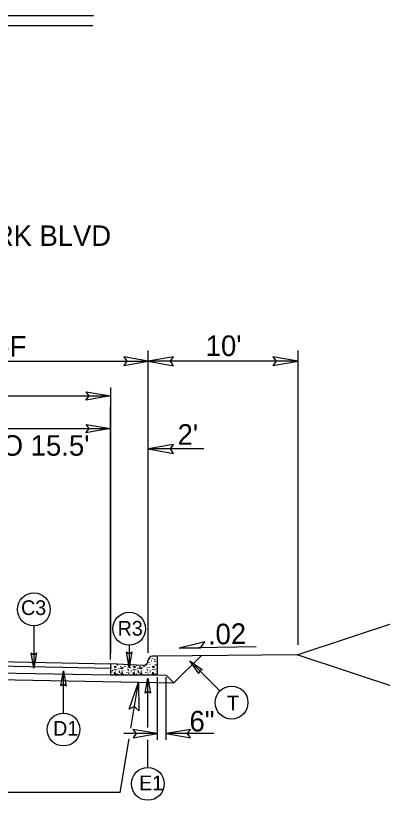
# Model space of a CAD drawing. Extents: x 958711 to 962106, y 831169 to 840840.
# Drawn here: x 959584.1 to 959723.1, y 835320.7 to 835618.4 of the extents above; entities that cross this region are included whole.
import ezdxf

# ---------------------------------------------------------------- set-up
doc = ezdxf.new("R2010")
doc.units = 0
for name, color, linetype in [('Old_Level_1', 7, 'Continuous'), ('Old_Level_11', 7, 'Continuous'), ('Old_Level_3', 7, 'Continuous'), ('Prop Dimension Text', 7, 'Continuous'), ('Typical ID Circle CELL', 7, 'Continuous'), ('Typical Terminator CELL', 7, 'Continuous'), ('Typical Text ID Circle CELL', 7, 'Continuous')]:
    doc.layers.add(name, color=color, linetype=linetype)

msp = doc.modelspace()

# ---------------------------------------------------------------- linework, layer by layer
at = {"layer": 'Old_Level_1'}
for p, q in [((959613.61, 835618.38), (959445.91, 835618.38)), ((959613.32, 835614.57), (959445.63, 835614.57)), ((959634.32, 835376.63), (959634.32, 835491.34)), ((959691.28, 835379.65), (959691.28, 835491.34)), ((959418.82, 835487.29), (959634.32, 835487.29)), ((959691.28, 835487.29), (959634.32, 835487.29)), ((959620.02, 835477.34), (959620.02, 835376.49)), ((959433.06, 835474.09), (959620.02, 835474.09)), ((959620.02, 835374.05), (959620.02, 835469.95)), ((959526.54, 835461.7), (959620.02, 835461.7)), ((959655.43, 835454.02), (959634.32, 835454.02)), ((959690.91, 835375.89), (959768.1, 835401.62)), ((959675.36, 835378.94), (959646.14, 835378.35)), ((959526.54, 835374.4), (959620.02, 835372.51)), ((959690.91, 835375.89), (959637.83, 835375.36)), ((959644.1, 835365.2), (959654.42, 835375.52)), ((959768.1, 835350.16), (959690.91, 835375.89)), ((959526.54, 835372.67), (959620.02, 835370.78)), ((959526.54, 835370.12), (959620.02, 835368.23)), ((959637.83, 835368.23), (959641.13, 835368.17)), ((959641.13, 835368.17), (959644.1, 835365.2)), ((959526.54, 835367.57), (959644.1, 835365.2)), ((959627.75, 835348.04), (959630.62, 835365.46)), ((959637.83, 835343.68), (959637.83, 835367.43)), ((959641.13, 835343.68), (959641.13, 835367.43)), ((959637.83, 835345.97), (959625.06, 835345.97)), ((959659.27, 835345.97), (959641.13, 835345.97)), ((959623.73, 835323.69), (959627.08, 835344.03)), ((959623.73, 835323.69), (959562.82, 835323.69))]:
    msp.add_line(p, q, dxfattribs=at)
msp.add_arc((959637.52, 835371.77), 0.309, 0, 90, dxfattribs=at)
at = {"layer": 'Old_Level_11'}
for p, q in [((959655.87, 835380.77), (959646.14, 835378.35)), ((959654.14, 835378.51), (959655.87, 835380.77)), ((959646.14, 835378.35), (959654.14, 835378.51))]:
    msp.add_line(p, q, dxfattribs=at)
for points in [[(959643.93, 835488.94), (959634.32, 835487.29), (959643.99, 835485.57), (959642.76, 835487.29)], [(959681.68, 835485.63), (959691.28, 835487.29), (959681.62, 835489), (959682.85, 835487.29)], [(959643.93, 835455.67), (959634.32, 835454.02), (959643.99, 835452.3), (959642.76, 835454.02)], [(959627.1, 835355.32), (959630.62, 835365.46), (959630.74, 835354.67), (959629.11, 835356.3)]]:
    msp.add_lwpolyline(points, close=True, dxfattribs=at)
at = {"layer": 'Old_Level_3'}
for p, q in [((959637.52, 835375.36), (959636.04, 835375.36)), ((959637.83, 835371.79), (959637.83, 835375.05)), ((959632.42, 835371.89), (959620.02, 835372.51)), ((959620.02, 835372.51), (959620.02, 835368.23)), ((959621.38, 835371.51), (959622, 835371.54)), ((959622, 835370.92), (959621.38, 835371.51)), ((959622, 835371.54), (959622, 835370.92)), ((959623.81, 835370.86), (959624.7, 835371.11)), ((959624.7, 835371.11), (959624.6, 835370.59)), ((959628.6, 835371.51), (959629.23, 835371.54)), ((959629.23, 835370.92), (959628.6, 835371.51)), ((959629.23, 835371.54), (959629.23, 835370.92)), ((959631.04, 835370.86), (959631.93, 835371.11)), ((959631.93, 835371.11), (959631.83, 835370.59)), ((959632.42, 835371.89), (959632.42, 835371.89)), ((959634.24, 835373), (959634.08, 835373.04)), ((959634.12, 835373.16), (959634.24, 835373)), ((959635.83, 835371.51), (959636.46, 835371.54)), ((959636.46, 835370.92), (959635.83, 835371.51)), ((959636.46, 835371.54), (959636.46, 835370.92)), ((959637.83, 835368.23), (959637.83, 835371.79)), ((959620.02, 835368.23), (959637.83, 835368.23)), ((959621.6, 835369.34), (959621.41, 835368.68)), ((959621.41, 835368.68), (959622.1, 835368.64)), ((959622.1, 835368.64), (959621.6, 835369.34)), ((959624.6, 835370.59), (959623.81, 835370.86)), ((959624.54, 835369.01), (959623.94, 835368.58)), ((959623.94, 835368.58), (959624.9, 835368.35)), ((959624.9, 835368.35), (959624.54, 835369.01)), ((959628.83, 835369.34), (959628.64, 835368.68)), ((959628.64, 835368.68), (959629.32, 835368.64)), ((959629.32, 835368.64), (959628.83, 835369.34)), ((959631.83, 835370.59), (959631.04, 835370.86)), ((959631.77, 835369.01), (959631.17, 835368.58)), ((959631.17, 835368.58), (959632.13, 835368.35)), ((959632.13, 835368.35), (959631.77, 835369.01)), ((959636.05, 835369.34), (959635.87, 835368.68)), ((959635.87, 835368.68), (959636.55, 835368.64)), ((959636.55, 835368.64), (959636.05, 835369.34))]:
    msp.add_line(p, q, dxfattribs=at)
for centre in [(959634.67, 835374.45), (959635.86, 835374.59), (959636.78, 835374.19), (959620.54, 835372.21), (959622.63, 835372.01), (959623.97, 835371.35), (959625.52, 835371.51), (959626.68, 835371.08), (959631.2, 835371.35), (959632.75, 835371.51), (959633.81, 835372.17), (959633.91, 835371.08), (959634.63, 835373.07), (959635, 835372.21), (959635.69, 835373.6), (959636.95, 835373.4), (959637.08, 835372.01), (959637.76, 835373.5), (959620.25, 835371.02), (959620.61, 835369.44), (959620.78, 835370.03), (959621.63, 835370.39), (959621.9, 835369.8), (959622.46, 835370.29), (959622.63, 835368.65), (959623.09, 835369.57), (959623.18, 835368.38), (959623.21, 835370.72), (959623.41, 835369.77), (959623.51, 835369.21), (959624.53, 835369.77), (959625.23, 835370.06), (959626.25, 835369.11), (959626.71, 835370.23), (959626.81, 835369.94), (959626.98, 835368.94), (959627.47, 835371.02), (959627.84, 835369.44), (959628, 835370.03), (959628.86, 835370.39), (959629.13, 835369.8), (959629.69, 835370.29), (959629.85, 835368.65), (959630.32, 835369.57), (959630.41, 835368.38), (959630.44, 835370.72), (959630.64, 835369.77), (959630.74, 835369.21), (959631.76, 835369.77), (959632.45, 835370.06), (959633.48, 835369.11), (959633.94, 835370.23), (959634.04, 835369.94), (959634.21, 835368.94), (959634.7, 835371.02), (959635.06, 835369.44), (959635.23, 835370.03), (959636.09, 835370.39), (959636.35, 835369.8), (959636.91, 835370.29), (959637.08, 835368.65), (959637.54, 835369.57), (959637.63, 835368.38), (959637.67, 835370.72)]:
    msp.add_circle(centre, 0.0464, dxfattribs=at)
for centre, radius, start, end in [((959636.04, 835373.58), 1.78, 90, 178.9266), ((959637.52, 835375.05), 0.309, 0, 90), ((959637.63, 835375.28), 0.0464, 169.6531, 280.3469), ((959626.58, 835372.17), 0.0464, 164.1199, 10.1626), ((959629.85, 835372.01), 0.0464, 162.062, 12.2205), ((959632.51, 835373.65), 1.76, 267.1376, 358.9266), ((959637.86, 835369.77), 0.0464, 150.4173, 209.5827)]:
    msp.add_arc(centre, radius, start, end, dxfattribs=at)
at = {"layer": 'Typical ID Circle CELL'}
for p, q in [((959590.97, 835386.9), (959590.97, 835370.81)), ((959627.14, 835379.55), (959627.14, 835371.25)), ((959661.56, 835362.16), (959650.18, 835373.54)), ((959602.22, 835353.75), (959602.22, 835369.84)), ((959634.2, 835348.3), (959634.2, 835367.07)), ((959634.2, 835333.13), (959634.2, 835343.63))]:
    msp.add_line(p, q, dxfattribs=at)
for centre in [(959590.97, 835393.12), (959627.14, 835385.78), (959665.96, 835357.76), (959602.22, 835347.53), (959634.2, 835326.91)]:
    msp.add_circle(centre, 6.23, dxfattribs=at)
at = {"layer": 'Typical Terminator CELL'}
for points in [[(959625.1, 835485.7), (959634.32, 835487.29), (959625.05, 835488.93), (959626.23, 835487.29)], [(959610.8, 835475.68), (959620.02, 835474.09), (959610.75, 835472.46), (959611.93, 835474.09)], [(959610.8, 835463.29), (959620.02, 835461.7), (959610.75, 835460.06), (959611.93, 835461.7)], [(959591.96, 835376.58), (959590.97, 835370.81), (959589.94, 835376.61), (959590.97, 835375.87)], [(959628.13, 835377.02), (959627.14, 835371.25), (959626.12, 835377.05), (959627.14, 835376.31)], [(959653.55, 835368.76), (959650.18, 835373.54), (959655, 835370.17), (959653.76, 835369.96)], [(959601.23, 835364.07), (959602.22, 835369.84), (959603.25, 835364.04), (959602.22, 835364.78)], [(959633.21, 835361.31), (959634.2, 835367.07), (959635.23, 835361.28), (959634.2, 835362.02)], [(959628.6, 835344.38), (959637.83, 835345.97), (959628.55, 835347.61), (959629.73, 835345.97)], [(959650.35, 835347.56), (959641.13, 835345.97), (959650.4, 835344.33), (959649.22, 835345.97)]]:
    msp.add_lwpolyline(points, close=True, dxfattribs=at)

# ---------------------------------------------------------------- texts
at = {"layer": 'Old_Level_1'}
msp.add_text("VAR. 70' F-F TO 33.2' F-F", height=7.8009, dxfattribs=at).set_placement((959466.52, 835489))
at = {"layer": 'Old_Level_3'}
for s, p in [("10'", (959656.16, 835489.24)), ("2'", (959645.49, 835455.58))]:
    msp.add_text(s, height=7.801, dxfattribs=at).set_placement(p)
at = {"layer": 'Prop Dimension Text'}
for s, height, rotation, p in [('-Y2A- PARK BLVD', 7.7675, 0, (959532.52, 835531.04)), ("VAR. 35' TO 15.5'", 7.8009, 0, (959528.66, 835451.42)), ('.02', 7.801, 1.1839, (959657.08, 835379.77)), ('6"', 7.801, 0, (959650.01, 835346.81))]:
    msp.add_text(s, height=height, rotation=rotation, dxfattribs=at).set_placement(p)
at = {"layer": 'Typical Text ID Circle CELL'}
for s, height, p in [('C3', 5.572, (959586.12, 835390.99)), ('R3', 5.572, (959622.76, 835383.15)), ('T', 5.57, (959664.25, 835354.78)), ('D1', 5.572, (959598.28, 835345.18)), ('E1', 5.572, (959630.9, 835324.52))]:
    msp.add_text(s, height=height, dxfattribs=at).set_placement(p)

doc.saveas('drawing.dxf')
